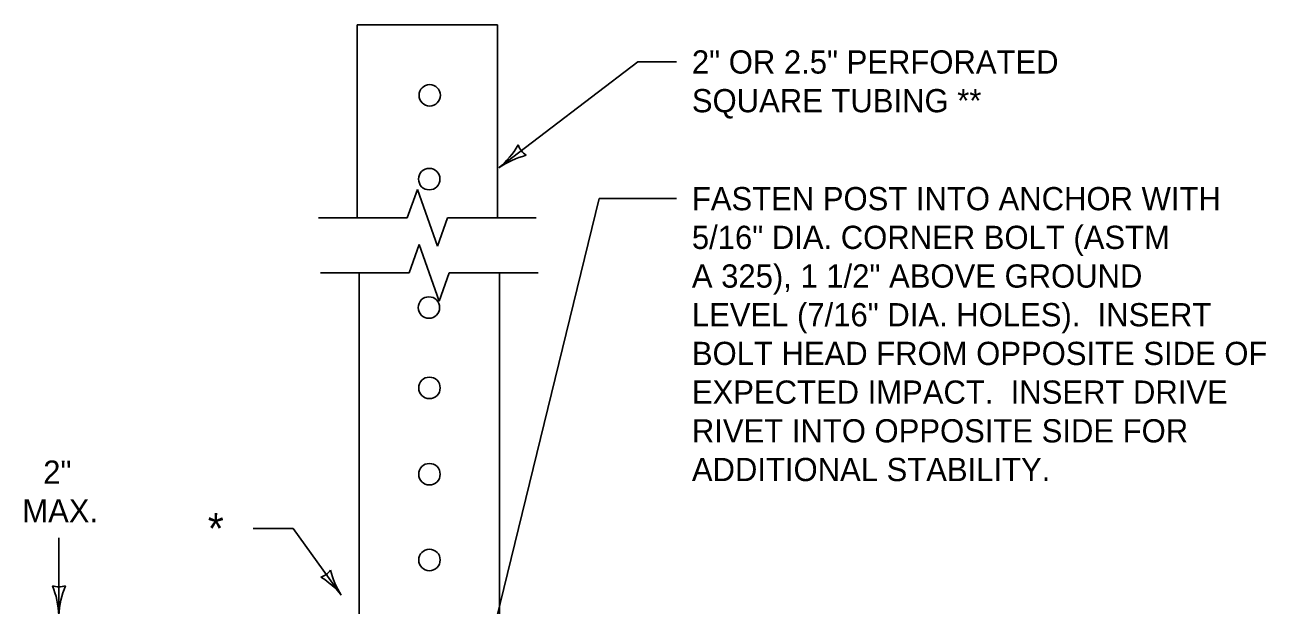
# Model space of a CAD drawing. Extents: x 49940 to 50043, y 49986 to 50011.
# Drawn here: x 49963.272 to 49966.484, y 49995.459 to 49996.959 of the extents above; entities that cross this region are included whole.
import ezdxf

# ---------------------------------------------------------------- set-up
doc = ezdxf.new("R2010")
doc.units = 0
for name, color, linetype in [('Level 1', 7, 'Continuous'), ('Level 2', 7, 'Continuous'), ('Level 3', 7, 'Continuous'), ('Level 6', 7, 'Continuous')]:
    doc.layers.add(name, color=color, linetype=linetype)

msp = doc.modelspace()

# ---------------------------------------------------------------- linework, layer by layer
at = {"layer": 'Level 1'}
msp.add_line((49964.1321, 49996.9589), (49964.4955, 49996.9589), dxfattribs=at)
for points in [[(49964.1321, 49996.9589), (49964.1321, 49996.4599)], [(49964.4955, 49996.4599), (49964.4955, 49996.9589)], [(49964.137, 49996.3178), (49964.137, 49995.4332), (49964.5004, 49995.4332), (49964.5002, 49996.3179)]]:
    msp.add_lwpolyline(points, dxfattribs=at)
for centre in [(49964.32, 49996.7768), (49964.3186, 49996.5602), (49964.3178, 49996.2284), (49964.3193, 49996.0208), (49964.3193, 49995.7977), (49964.3193, 49995.576)]:
    msp.add_circle(centre, 0.0277, dxfattribs=at)
at = {"layer": 'Level 3'}
for p, q in [((49964.4986, 49996.589), (49964.8581, 49996.863)), ((49964.8581, 49996.863), (49964.9582, 49996.863)), ((49964.4785, 49995.3662), (49964.7583, 49996.5098)), ((49964.7583, 49996.5098), (49964.9582, 49996.5098)), ((49963.8635, 49995.657), (49963.9668, 49995.657)), ((49963.9668, 49995.657), (49964.091, 49995.4852)), ((49963.3606, 49995.433), (49963.3606, 49995.633))]:
    msp.add_line(p, q, dxfattribs=at)
for centre, radius, start, end in [((49964.3484, 49996.7671), 0.233, 310.1409, 329.3907), ((49964.6006, 49996.6667), 0.0548, 199.4524, 235.1747), ((49964.626, 49996.4068), 0.2223, 104.7696, 124.9531), ((49964.0234, 49995.5787), 0.0493, 288.0017, 323.724), ((49963.9273, 49995.3541), 0.2097, 38.6902, 57.94), ((49964.2579, 49995.5957), 0.2001, 193.3189, 213.5024), ((49963.3606, 49995.5612), 0.0548, 252.1388, 287.8612), ((49963.1279, 49995.4215), 0.233, 2.8273, 22.0772), ((49963.5828, 49995.4239), 0.2223, 157.456, 177.6395)]:
    msp.add_arc(centre, radius, start, end, dxfattribs=at)
at = {"layer": 'Level 6'}
for p, q in [((49964.2879, 49996.533), (49964.262, 49996.4599)), ((49964.2879, 49996.533), (49964.3138, 49996.4599)), ((49964.0321, 49996.4599), (49964.262, 49996.4599)), ((49964.3138, 49996.4599), (49964.3397, 49996.3868)), ((49964.3656, 49996.4599), (49964.3397, 49996.3868)), ((49964.3656, 49996.4599), (49964.5955, 49996.4599)), ((49964.2927, 49996.3909), (49964.2668, 49996.3178)), ((49964.2927, 49996.3909), (49964.3186, 49996.3178)), ((49964.0371, 49996.3178), (49964.2668, 49996.3178)), ((49964.3186, 49996.3178), (49964.3445, 49996.2447)), ((49964.3704, 49996.3178), (49964.3445, 49996.2447)), ((49964.3704, 49996.3179), (49964.6001, 49996.3179))]:
    msp.add_line(p, q, dxfattribs=at)

# ---------------------------------------------------------------- texts
at = {"layer": 'Level 2'}
for s, p in [('2" OR 2.5" PERFORATED', (49964.9982, 49996.833)), ('SQUARE TUBING **', (49964.9982, 49996.733)), ('FASTEN POST INTO ANCHOR WITH', (49964.9982, 49996.4798)), ('5/16" DIA. CORNER BOLT (ASTM', (49964.9982, 49996.3798)), ('A 325), 1 1/2" ABOVE GROUND', (49964.9982, 49996.2798)), ('LEVEL (7/16" DIA. HOLES).  INSERT', (49964.9982, 49996.1798)), ('BOLT HEAD FROM OPPOSITE SIDE OF', (49964.9982, 49996.0798)), ('EXPECTED IMPACT.  INSERT DRIVE', (49964.9982, 49995.9798)), ('RIVET INTO OPPOSITE SIDE FOR', (49964.9982, 49995.8798)), ('2"', (49963.32, 49995.773)), ('ADDITIONAL STABILITY.', (49964.9982, 49995.7798)), ('MAX.', (49963.2658, 49995.673))]:
    msp.add_text(s, height=0.06, dxfattribs=at).set_placement(p)
msp.add_text('*', height=0.08, rotation=359.5, dxfattribs=at).set_placement((49963.7451, 49995.6177))

doc.saveas('drawing.dxf')
